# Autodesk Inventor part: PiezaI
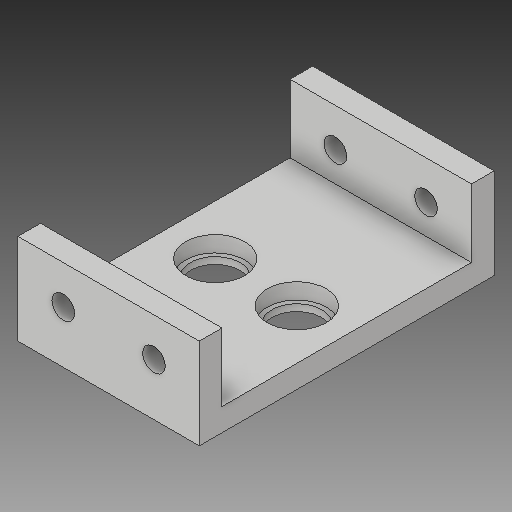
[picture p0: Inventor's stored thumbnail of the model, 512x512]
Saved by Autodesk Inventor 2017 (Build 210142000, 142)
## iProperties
Part Number: PiezaI
Material: Genérico
Document SubType Name: Modeling
Designer: Jaime
Density: 1 g/cm^3
Appearance: Valor por defecto
Mass: 139.145 g
Surface Area: 364.66 cm^2
Volume: 139.145 cm^3
Author: Jaime
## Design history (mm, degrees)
sketch "Boceto2"
  geometry: L1 (-40, 55)-(40, 55); L2 (40, 55)-(40, -55); L3 (40, -55)-(-40, -55); L4 (-40, -55)-(-40, 55); 3 further points
  constraints: 8 end point, 2 midpoint, 2 parallel, 1 horizontal, 1 horizontal alignment, 1 perpendicular, 1 vertical alignment
  dimensions: "d0" = 80 distance of L1.start L1.end; "d1" = 110 distance of L1.end L2.end
extrude "Extrusión1" new body sketch "Boceto2" distance "d2" = 10; taper "d3" = 0 deg
sketch "Boceto3"
  geometry: L1 (80, 0)-(0, 0) reference; L2 (0, 0)-(80, 0); L3 (80, 0)-(80, 40); L4 (80, 40)-(0, 40); L5 (0, 40)-(0, 0); L6 (80, 0)-(80, 10) reference; 1 further point
  constraints: 8 end point, 2 parallel, 1 collinear, 1 horizontal, 1 perpendicular
  dimensions: "d5" = 40 distance of L3.end L2.end
extrude "Extrusión2" join sketch "Boceto3" distance "d6" = 10; taper "d7" = 0 deg
sketch "Boceto5"
  geometry: L1 (0, 0)-(80, 0); L2 (80, 0)-(80, 40); L3 (80, 40)-(0, 40); L4 (0, 40)-(0, 0); L5 (80, 0)-(80, 10) reference; L6 (0, 0)-(0, 10) reference; L7 (80, 0)-(0, 0) reference; 1 further point
  constraints: 8 end point, 3 collinear, 2 parallel, 1 horizontal, 1 perpendicular
  dimensions: "d9" = 40 distance of L2.end L1.end
extrude "Extrusión3" join sketch "Boceto5" distance "d10" = 10; taper "d11" = 0 deg
sketch "Boceto6"
  geometry: L1 (40, -55)-(40, 55) reference; C1 r 13 at (18, 0); 2 further points
  constraints: 1 centre point, 1 coincident, 1 horizontal alignment, 1 midpoint
  dimensions: "d12" = 26 diameter of C1; "d18" = 22 distance from line of L1 point (18, 0)
extrude "Extrusión4" cut sketch "Boceto6" distance "d13" = 7; taper "d14" = 0 deg
sketch "Boceto7"
  geometry: C1 r 11 at (0, 0); C2 r 13 at (0, 0) reference
  constraints: 1 centre point, 1 concentric
  dimensions: "d15" = 22 diameter of C1
extrude "Extrusión5" cut sketch "Boceto7" stored distance "d16" = 8; taper "d17" = 0 deg
pattern_linear "Patrón rectangular1" dims "d21" = 36
sketch "Boceto8"
  geometry: L1 (0, 40)-(0, 0) reference; L2 (80, 0)-(80, 40) reference; L3 (80, 40)-(0, 40) reference; C1 r 5 at (20, 23); C2 r 5 at (60, 23); 2 further points
  constraints: 2 centre point, 1 horizontal alignment
  dimensions: "d22" = 10 diameter of C1; "d23" = 10 diameter of C2; "d24" = 20 distance from line of L1 C1.centre; "d25" = 20 distance from line of L2 C2.centre; "d29" = 13 vertical distance of point (80, 10) C2.centre
extrude "Extrusión6" cut sketch "Boceto8" stored distance "d27" = 8; taper "d28" = 0 deg
node "Sólido1"
